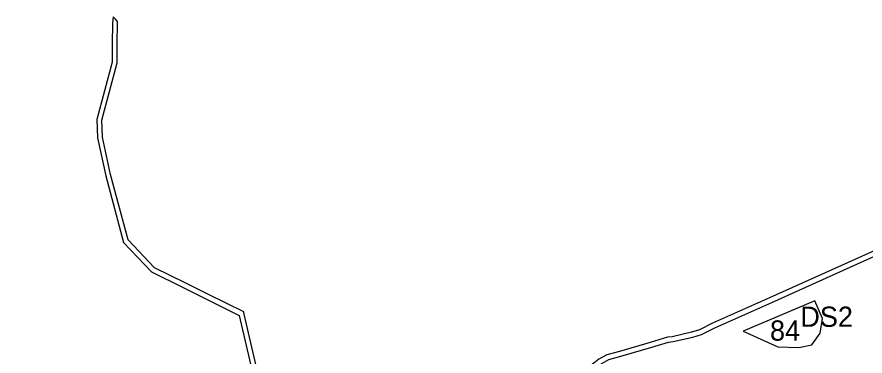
# Model space of a CAD drawing. Extents: x -477001 to -465642, y -1158278 to -1150672.
# Drawn here: x -469981 to -469477, y -1153423 to -1153222 of the extents above; entities that cross this region are included whole.
import ezdxf

# ---------------------------------------------------------------- set-up
doc = ezdxf.new("R2010")
doc.units = 0
for name, color, linetype in [('VPS_id', 7, 'Continuous'), ('VPS_n', 7, 'Continuous'), ('vyvlastneni_n', 7, 'Continuous')]:
    doc.layers.add(name, color=color, linetype=linetype)

msp = doc.modelspace()

# ---------------------------------------------------------------- linework, layer by layer
at = {"layer": 'VPS_n'}
for p, q in [((-469923.67, -1153221.89), (-469924.03, -1153225.48)), ((-469506.73, -1153390.45), (-469549.34, -1153408.46))]:
    msp.add_line(p, q, dxfattribs=at)
for points in [[(-469920.92, -1153224.53), (-469922.25, -1153223.26), (-469923.67, -1153221.89)], [(-469924.03, -1153225.48), (-469924.14, -1153237.9), (-469924.24, -1153248.64), (-469933.25, -1153282.8), (-469932.94, -1153293.65), (-469928.03, -1153316.16), (-469917.44, -1153355.79), (-469900.76, -1153373.26), (-469882.11, -1153382.51), (-469868.23, -1153389.4), (-469848.65, -1153399.12), (-469823.97, -1153505.24), (-469823.97, -1153505.33), (-469826.25, -1153526.64), (-469829.73, -1153533.5), (-469829.85, -1153539.94), (-469828.88, -1153541.96), (-469862.41, -1153553.77), (-469980.74, -1153653.15), (-469975.5, -1153676.95), (-469968.34, -1153709.45), (-469962.14, -1153739.93)], [(-469820.96, -1153504.92), (-469845.73, -1153398.41), (-469846.04, -1153397.06), (-469866.9, -1153386.71), (-469880.78, -1153379.82), (-469898.95, -1153370.81), (-469914.74, -1153354.27), (-469925.11, -1153315.45), (-469929.95, -1153293.28), (-469930.24, -1153283.15), (-469921.24, -1153249.04), (-469921.14, -1153237.93), (-469921.03, -1153225.64), (-469920.92, -1153224.53)], [(-469434.21, -1153343.98), (-469486.99, -1153367.69), (-469533.66, -1153388.67), (-469567.53, -1153403.78), (-469575.25, -1153407.62), (-469580.07, -1153409.16), (-469591.53, -1153411.76), (-469594.27, -1153412.12), (-469604.55, -1153415.16), (-469622.77, -1153420.54), (-469630.33, -1153422.61), (-469635.05, -1153425.16), (-469641.99, -1153430.58), (-469647.94, -1153435.55), (-469649.29, -1153436.68)], [(-469691.53, -1153485.91), (-469687.93, -1153481.41), (-469685.68, -1153478.75), (-469647.24, -1153438.88), (-469646.02, -1153437.85), (-469640.1, -1153432.91), (-469633.4, -1153427.68), (-469629.21, -1153425.41), (-469621.95, -1153423.43), (-469603.7, -1153418.04), (-469593.65, -1153415.06), (-469591, -1153414.72), (-469579.28, -1153412.06), (-469574.12, -1153410.41), (-469566.25, -1153406.49), (-469532.43, -1153391.41), (-469485.76, -1153370.43), (-469433.06, -1153346.75)], [(-469549.34, -1153408.46), (-469528.69, -1153417.85), (-469516.29, -1153418.24), (-469508.52, -1153416.51), (-469503.58, -1153409.7), (-469502.26, -1153401.06), (-469506.73, -1153390.45)]]:
    msp.add_lwpolyline(points, dxfattribs=at)
at = {"layer": 'vyvlastneni_n'}
for p, q in [((-469923.67, -1153221.89), (-469924.03, -1153225.48)), ((-469506.73, -1153390.45), (-469549.34, -1153408.46))]:
    msp.add_line(p, q, dxfattribs=at)
for points in [[(-469920.92, -1153224.53), (-469922.25, -1153223.26), (-469923.67, -1153221.89)], [(-469924.03, -1153225.48), (-469924.14, -1153237.9), (-469924.24, -1153248.64), (-469933.25, -1153282.8), (-469932.94, -1153293.65), (-469928.03, -1153316.16), (-469917.44, -1153355.79), (-469900.76, -1153373.26), (-469882.11, -1153382.51), (-469868.23, -1153389.4), (-469848.65, -1153399.12), (-469823.97, -1153505.24), (-469823.97, -1153505.33), (-469826.25, -1153526.64), (-469829.73, -1153533.5), (-469829.85, -1153539.94), (-469828.88, -1153541.96), (-469862.41, -1153553.77), (-469980.74, -1153653.15), (-469975.5, -1153676.95), (-469968.34, -1153709.45), (-469962.14, -1153739.93)], [(-469820.96, -1153504.92), (-469845.73, -1153398.41), (-469846.04, -1153397.06), (-469866.9, -1153386.71), (-469880.78, -1153379.82), (-469898.95, -1153370.81), (-469914.74, -1153354.27), (-469925.11, -1153315.45), (-469929.95, -1153293.28), (-469930.24, -1153283.15), (-469921.24, -1153249.04), (-469921.14, -1153237.93), (-469921.03, -1153225.64), (-469920.92, -1153224.53)], [(-469434.21, -1153343.98), (-469486.99, -1153367.69), (-469533.66, -1153388.67), (-469567.53, -1153403.78), (-469575.25, -1153407.62), (-469580.07, -1153409.16), (-469591.53, -1153411.76), (-469594.27, -1153412.12), (-469604.55, -1153415.16), (-469622.77, -1153420.54), (-469630.33, -1153422.61), (-469635.05, -1153425.16), (-469641.99, -1153430.58), (-469647.94, -1153435.55), (-469649.29, -1153436.68)], [(-469691.53, -1153485.91), (-469687.93, -1153481.41), (-469685.68, -1153478.75), (-469647.24, -1153438.88), (-469646.02, -1153437.85), (-469640.1, -1153432.91), (-469633.4, -1153427.68), (-469629.21, -1153425.41), (-469621.95, -1153423.43), (-469603.7, -1153418.04), (-469593.65, -1153415.06), (-469591, -1153414.72), (-469579.28, -1153412.06), (-469574.12, -1153410.41), (-469566.25, -1153406.49), (-469532.43, -1153391.41), (-469485.76, -1153370.43), (-469433.06, -1153346.75)], [(-469549.34, -1153408.46), (-469528.69, -1153417.85), (-469516.29, -1153418.24), (-469508.52, -1153416.51), (-469503.58, -1153409.7), (-469502.26, -1153401.06), (-469506.73, -1153390.45)]]:
    msp.add_lwpolyline(points, dxfattribs=at)

# ---------------------------------------------------------------- texts
at = {"layer": 'VPS_id'}
msp.add_text('84', height=12, dxfattribs=at).set_placement((-469533.43, -1153414.1))
at = {"layer": 'VPS_n'}
msp.add_text('DS2', height=12, dxfattribs=at).set_placement((-469515.39, -1153405.9))

doc.saveas('drawing.dxf')
